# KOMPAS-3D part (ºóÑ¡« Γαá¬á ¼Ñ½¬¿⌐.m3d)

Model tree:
1. Эскиз:1
2. Операция выдавливания:1
     Расстояние 1 = 1.9
3. Эскиз:3
4. Операция выдавливания:3
     Расстояние 1 = 3.5
5. Эскиз:4
6. Вырезать элемент выдавливания:1
     Расстояние 1 = 0.5
7. Эскиз:5
8. Вырезать элемент выдавливания:2
     Расстояние 1 = 2.5
9. Эскиз:6
10. Вырезать элемент выдавливания:3
     Расстояние 1 = 2.5
11. Эскиз:7
12. Вырезать элемент выдавливания:4
     Расстояние 1 = 2.5
13. Эскиз:8
14. Вырезать элемент выдавливания:5
     Расстояние 1 = 2.5
15. Эскиз:9
16. Вырезать элемент выдавливания:6
     Расстояние 1 = 3
17. Эскиз:10
18. Вырезать элемент выдавливания:7
     Расстояние 1 = 18.2
19. Эскиз:11
20. Вырезать элемент выдавливания:8
     Расстояние 1 = 6
21. Эскиз:13
22. Вырезать элемент выдавливания:9
     Расстояние 1 = 4
23. Эскиз:14
24. Вырезать элемент выдавливания:10
     Расстояние 1 = 0.6
25. Эскиз:15
26. Операция выдавливания:4
     Расстояние 1 = 0.4
27. Эскиз:17
28. Операция выдавливания:6
     Расстояние 1 = 18.2
29. Эскиз:18
30. Вырезать элемент выдавливания:11
     Расстояние 1 = 5.4
31. Эскиз:19
32. Вырезать элемент выдавливания:12
     Расстояние 1 = 2.6
33. Эскиз:20
34. Операция выдавливания:7
     Расстояние 1 = 6.4
35. Эскиз:21
36. Операция выдавливания:8
     Расстояние 1 = 6.4; Расстояние 2 = 2.6
37. Эскиз:23
38. Операция выдавливания:9
     Расстояние 1 = 6.4; Расстояние 2 = 2.5
39. Эскиз:24
40. Вырезать элемент выдавливания:13
     Расстояние 1 = 0.6
41. Эскиз:25
42. Вырезать элемент выдавливания:14
     Расстояние 2 = 18.2
43. Зеркальный массив:1  (with: Операция выдавливания:1, Операция выдавливания:3, Вырезать элемент выдавливания:1, Вырезать элемент выдавливания:2, Вырезать элемент выдавливания:3, Вырезать элемент выдавливания:4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)  (labels: Экземпляр ( 1 ); Экземпляр ( 2 ))
44. Скругление:1
     Радиус = 0.6
45. Скругление:2
     Радиус = 0.2
46. Скругление:3
     Радиус = 0.2
47. Скругление:4
     Радиус = 0.2
48. Скругление:5
     Радиус = 0.2
49. Скругление:6
     Радиус = 0.2; Хорда = 0.2
50. Скругление:7
     Радиус = 0.2; Хорда = 0.2
51. Скругление:9
     Радиус = 0.2; Хорда = 0.2
52. Скругление:10
     Радиус = 0.2; Хорда = 0.2
53. Скругление:11
     Радиус = 0.2; Хорда = 0.2
54. Скругление:12
     Радиус = 0.2; Хорда = 0.2
55. Скругление:13
     Радиус = 0.2; Хорда = 0.2
56. Скругление:14
     Радиус = 0.2; Хорда = 0.2
57. Скругление:15
     Радиус = 0.2; Хорда = 0.2
58. Скругление:16
     Радиус = 0.2; Хорда = 0.2
59. Скругление:17
     Радиус = 0.2; Хорда = 0.2
60. Скругление:18
     Радиус = 0.2; Хорда = 0.2
61. Скругление:19
     Радиус = 0.2; Хорда = 0.2
62. Скругление:20
     Радиус = 0.2; Хорда = 0.2
63. Скругление:21
     Радиус = 0.2; Хорда = 0.2
64. Скругление:22
     Радиус = 0.2; Хорда = 0.2
65. Скругление:23
     Радиус = 0.1; Хорда = 0.2
66. Скругление:24
     Радиус = 0.1; Хорда = 0.2
67. Скругление:25
     Радиус = 0.1; Хорда = 0.2
68. Фаска:1
     Угол = 81.3844; Длина 1 = 1; Длина 2 = 6.6
69. Фаска:2
     Угол = 8.61565; Длина 1 = 6.6; Длина 2 = 1
70. Фаска:3
     Угол = 82.875; Длина 1 = 0.8; Длина 2 = 6.4
71. Фаска:4
     Угол = 7.12502; Длина 1 = 6.4; Длина 2 = 0.8
72. Скругление:32
     Радиус = 0.2; Полуось 2 = 0.4; Хорда = 0.5
73. Скругление:33
     Радиус = 0.4; Полуось 2 = 0.4; Хорда = 0.5

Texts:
  трак малый 1
  Сплав АЛ8  ГОСТ 1583-93
  Экземпляр ( 1 )
  Экземпляр ( 2 )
